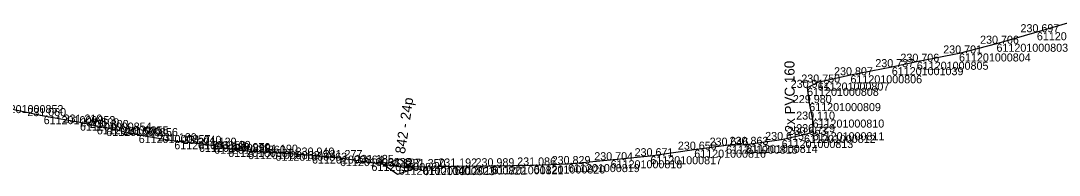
# Model space of a CAD drawing. Extents: x -771040 to -768909, y -1052366 to -1050115.
# Drawn here: x -770606.1 to -770450.8, y -1050305.1 to -1050282.1 of the extents above; entities that cross this region are included whole.
import ezdxf

# ---------------------------------------------------------------- set-up
doc = ezdxf.new("R2010")
doc.units = 0
for name, color, linetype in [('Vrstva 28', 7, 'Continuous'), ('Vrstva 35', 7, 'Continuous'), ('Vrstva 60', 7, 'Continuous'), ('Vrstva 61', 7, 'Continuous')]:
    doc.layers.add(name, color=color, linetype=linetype)

msp = doc.modelspace()

# ---------------------------------------------------------------- linework, layer by layer
at = {"layer": 'Vrstva 28'}
for p, q in [((-770551.88, -1050303.55), (-770549.41, -1050302.72)), ((-770549.41, -1050302.72), (-770547.27, -1050304.19)), ((-770546.11, -1050304.35), (-770553.03, -1050303.39)), ((-770549.73, -1050305.02), (-770551.88, -1050303.55)), ((-770547.27, -1050304.19), (-770549.73, -1050305.02))]:
    msp.add_line(p, q, dxfattribs=at)
for points in [[(-770448.36, -1050282.07), (-770454.15, -1050283.78), (-770460.19, -1050285.5), (-770465.79, -1050286.95), (-770472.1, -1050288.19), (-770475.84, -1050289), (-770482.02, -1050290.21), (-770486.92, -1050291.3)], [(-770486.92, -1050291.3), (-770488.5, -1050292.09), (-770488.18, -1050294.37), (-770487.68, -1050296.83), (-770487.66, -1050298.72), (-770488.96, -1050299.12)], [(-770562.52, -1050302.21), (-770567.98, -1050301.78), (-770572.09, -1050301.54), (-770575.05, -1050301.22), (-770577.15, -1050300.74), (-770579.41, -1050300.46), (-770583.1, -1050300.07), (-770588.42, -1050299.14), (-770593.28, -1050298.09), (-770594.69, -1050297.84), (-770597.21, -1050297.28), (-770602.63, -1050296.32), (-770610.4, -1050294.67)], [(-770488.96, -1050299.12), (-770492.31, -1050299.88), (-770497.64, -1050300.61), (-770500.62, -1050300.73), (-770505.37, -1050301.33), (-770511.93, -1050302.31), (-770517.87, -1050302.91), (-770524.24, -1050303.48), (-770529.39, -1050303.69), (-770535.62, -1050303.81), (-770541.19, -1050303.84), (-770545.9, -1050303.93), (-770549.57, -1050303.87), (-770553.63, -1050303.31), (-770558.33, -1050302.58), (-770562.52, -1050302.21)]]:
    msp.add_lwpolyline(points, dxfattribs=at)
at = {"layer": 'Vrstva 35'}
msp.add_lwpolyline([(-770486.92, -1050291.3), (-770488.5, -1050292.09), (-770488.18, -1050294.37), (-770487.68, -1050296.83), (-770487.66, -1050298.72), (-770488.96, -1050299.12)], dxfattribs=at)
at = {"layer": 'Vrstva 60'}
for p, q in [((-770454.15, -1050283.78), (-770454.15, -1050283.78)), ((-770460.19, -1050285.5), (-770460.19, -1050285.5)), ((-770465.79, -1050286.95), (-770465.79, -1050286.95)), ((-770475.84, -1050289), (-770475.84, -1050289)), ((-770472.1, -1050288.19), (-770472.1, -1050288.19)), ((-770482.02, -1050290.21), (-770482.02, -1050290.21)), ((-770488.5, -1050292.09), (-770488.5, -1050292.09)), ((-770486.92, -1050291.3), (-770486.92, -1050291.3)), ((-770488.18, -1050294.37), (-770488.18, -1050294.37)), ((-770602.63, -1050296.32), (-770602.63, -1050296.32)), ((-770487.68, -1050296.83), (-770487.68, -1050296.83)), ((-770597.21, -1050297.28), (-770597.21, -1050297.28)), ((-770594.69, -1050297.84), (-770594.69, -1050297.84)), ((-770593.28, -1050298.09), (-770593.28, -1050298.09)), ((-770588.42, -1050299.14), (-770588.42, -1050299.14)), ((-770583.1, -1050300.07), (-770583.1, -1050300.07)), ((-770492.31, -1050299.88), (-770492.31, -1050299.88)), ((-770488.96, -1050299.12), (-770488.96, -1050299.12)), ((-770487.66, -1050298.72), (-770487.66, -1050298.72)), ((-770579.41, -1050300.46), (-770579.41, -1050300.46)), ((-770577.15, -1050300.74), (-770577.15, -1050300.74)), ((-770575.05, -1050301.22), (-770575.05, -1050301.22)), ((-770572.09, -1050301.54), (-770572.09, -1050301.54)), ((-770505.37, -1050301.33), (-770505.37, -1050301.33)), ((-770500.62, -1050300.73), (-770500.62, -1050300.73)), ((-770497.64, -1050300.61), (-770497.64, -1050300.61)), ((-770567.98, -1050301.78), (-770567.98, -1050301.78)), ((-770562.52, -1050302.21), (-770562.52, -1050302.21)), ((-770558.33, -1050302.58), (-770558.33, -1050302.58)), ((-770553.63, -1050303.31), (-770553.63, -1050303.31)), ((-770517.87, -1050302.91), (-770517.87, -1050302.91)), ((-770511.93, -1050302.31), (-770511.93, -1050302.31)), ((-770549.57, -1050303.87), (-770549.57, -1050303.87)), ((-770545.9, -1050303.93), (-770545.9, -1050303.93)), ((-770541.19, -1050303.84), (-770541.19, -1050303.84)), ((-770535.62, -1050303.81), (-770535.62, -1050303.81)), ((-770529.39, -1050303.69), (-770529.39, -1050303.69)), ((-770524.24, -1050303.48), (-770524.24, -1050303.48))]:
    msp.add_line(p, q, dxfattribs=at)

# ---------------------------------------------------------------- texts
at = {"layer": 'Vrstva 28'}
msp.add_text('842 - 24p', height=1.5, rotation=81.2856, dxfattribs=at).set_placement((-770548.63, -1050302.03))
at = {"layer": 'Vrstva 35'}
msp.add_text('2x PVC 160', height=1.5, rotation=90.5156, dxfattribs=at).set_placement((-770490.3, -1050298.74))
at = {"layer": 'Vrstva 60'}
for s, p in [('611201000802', (-770454.15, -1050284.98)), ('611201000803', (-770460.19, -1050286.7)), ('611201000804', (-770465.79, -1050288.15)), ('611201001039', (-770475.84, -1050290.2)), ('611201000805', (-770472.1, -1050289.39)), ('611201000806', (-770482.02, -1050291.41)), ('611201000808', (-770488.5, -1050293.29)), ('611201000807', (-770486.92, -1050292.5)), ('611201000852', (-770610.4, -1050295.87)), ('611201000809', (-770488.18, -1050295.57)), ('611201000853', (-770602.63, -1050297.52)), ('611201000810', (-770487.68, -1050298.03)), ('611201000854', (-770597.21, -1050298.48)), ('611201000855', (-770594.69, -1050299.04)), ('611201000856', (-770593.28, -1050299.29)), ('611201000857', (-770588.42, -1050300.34)), ('611201000858', (-770583.1, -1050301.27)), ('611201000813', (-770492.31, -1050301.08)), ('611201000812', (-770488.96, -1050300.32)), ('611201000811', (-770487.66, -1050299.92)), ('611201000859', (-770579.41, -1050301.66)), ('611201000860', (-770577.15, -1050301.94)), ('611201000861', (-770575.05, -1050302.42)), ('611201000862', (-770572.09, -1050302.74)), ('611201000863', (-770567.98, -1050302.98)), ('611201000816', (-770505.37, -1050302.53)), ('611201000815', (-770500.62, -1050301.93)), ('611201000814', (-770497.64, -1050301.81)), ('611201000864', (-770562.52, -1050303.41)), ('611201000825', (-770558.33, -1050303.78)), ('611201000824', (-770553.63, -1050304.51)), ('611201000818', (-770517.87, -1050304.11)), ('611201000817', (-770511.93, -1050303.51)), ('611201001040', (-770549.57, -1050305.07)), ('611201000823', (-770545.9, -1050305.13)), ('611201000822', (-770541.19, -1050305.04)), ('611201000821', (-770535.62, -1050305.01)), ('611201000820', (-770529.39, -1050304.89)), ('611201000819', (-770524.24, -1050304.68))]:
    msp.add_text(s, height=1.2, dxfattribs=at).set_placement(p)
at = {"layer": 'Vrstva 61'}
for s, p in [('230.697', (-770456.6, -1050283.78)), ('230.706', (-770462.64, -1050285.5)), ('230.701', (-770468.15, -1050286.95)), ('230.737', (-770478.3, -1050289)), ('230.706', (-770474.55, -1050288.19)), ('230.807', (-770484.47, -1050290.21)), ('230.912', (-770490.95, -1050292.09)), ('230.750', (-770489.37, -1050291.3)), ('229.980', (-770490.63, -1050294.37)), ('231.060', (-770605.08, -1050296.32)), ('231.210', (-770599.66, -1050297.28)), ('231.500', (-770597.14, -1050297.84)), ('231.800', (-770595.73, -1050298.09)), ('230.110', (-770490.13, -1050296.83)), ('231.580', (-770590.87, -1050299.14)), ('230.653', (-770491.41, -1050299.12)), ('230.729', (-770490.12, -1050298.72)), ('231.180', (-770585.55, -1050300.07)), ('231.040', (-770581.86, -1050300.46)), ('231.120', (-770579.6, -1050300.74)), ('231.100', (-770577.5, -1050301.22)), ('230.650', (-770507.82, -1050301.33)), ('230.646', (-770503.08, -1050300.73)), ('230.863', (-770500.09, -1050300.61)), ('230.615', (-770494.77, -1050299.88)), ('230.970', (-770574.54, -1050301.54)), ('231.190', (-770570.43, -1050301.78)), ('230.940', (-770564.97, -1050302.21)), ('231.277', (-770560.78, -1050302.58)), ('230.704', (-770520.32, -1050302.91)), ('230.671', (-770514.29, -1050302.31)), ('231.185', (-770556.09, -1050303.31)), ('231.197', (-770552.02, -1050303.87)), ('231.350', (-770548.35, -1050303.93)), ('231.192', (-770543.64, -1050303.84)), ('230.989', (-770538.07, -1050303.81)), ('231.086', (-770531.84, -1050303.69)), ('230.829', (-770526.69, -1050303.48))]:
    msp.add_text(s, height=1.2, dxfattribs=at).set_placement(p)

doc.saveas('drawing.dxf')
